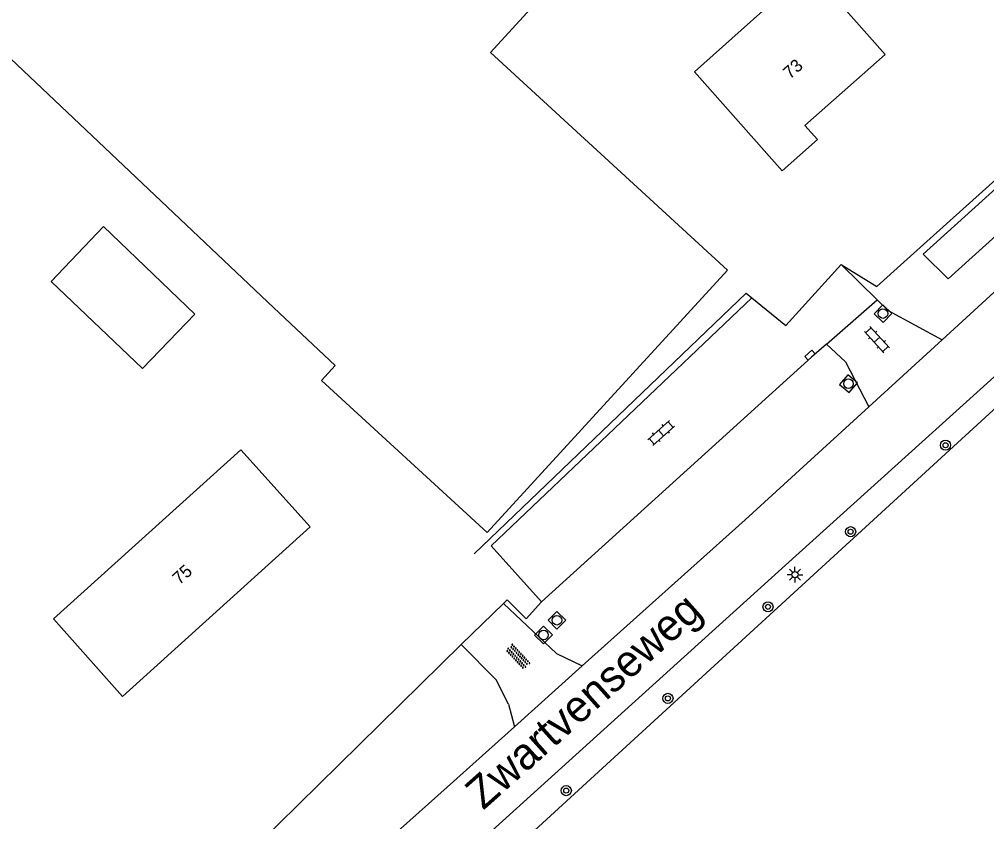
# Model space of a CAD drawing. Extents: x 128999 to 131010, y 395498 to 399007.
# Drawn here: x 129740 to 129816.6, y 397459.3 to 397522.8 of the extents above; entities that cross this region are included whole.
import ezdxf

# ---------------------------------------------------------------- set-up
doc = ezdxf.new("R2010")
doc.units = 0
for name, color, linetype in [('gg-afsc-erfafscheiding', 7, 'Continuous'), ('gg-afsc-hekwerk', 7, 'Continuous'), ('gg-anno-huisnummerreeks BGT', 7, 'Continuous'), ('gg-anno-openbare ruimte label', 7, 'Continuous'), ('gg-bbg-bijgebouw', 7, 'Continuous'), ('gg-bbg-hoofdgebouw', 7, 'Continuous'), ('gg-knt-onverhard', 7, 'Continuous'), ('gg-knt-verharding', 7, 'Continuous'), ('gg-kntw-bovenkant insteek waterloop', 7, 'Continuous'), ('gt-grn-groengrens', 7, 'Continuous'), ('gt-grn-vlakafsluiter', 7, 'Continuous'), ('gt-symb-boom', 7, 'Continuous'), ('gt-symb-klinker verharding', 7, 'Continuous'), ('gt-symb-kolk', 7, 'Continuous'), ('gt-symb-lichtmast', 7, 'Continuous'), ('gt-symb-overige verharding', 7, 'Continuous'), ('gt-symb-rioolschacht', 7, 'Continuous')]:
    doc.layers.add(name, color=color, linetype=linetype)

# ---------------------------------------------------------------- blocks, each defined once
blk = doc.blocks.new('gt0-BOOM')
at = {"layer": 'gt-symb-boom'}
for radius in [0.4, 0.2]:
    blk.add_circle((0, 0), radius, dxfattribs=at)
blk = doc.blocks.new('gt0-RS')
at = {"layer": 'gt-symb-rioolschacht'}
blk.add_lwpolyline([(-0.5, -0.5), (0.5, -0.5), (0.5, 0.5), (-0.5, 0.5)], close=True, dxfattribs=at)
blk.add_circle((0, 0), 0.375, dxfattribs=at)
blk = doc.blocks.new('gt0-LMAST')
at = {"layer": 'gt-symb-lichtmast'}
for p, q in [((-0.182, 0.173), (-0.447, 0.438)), ((-0.005, 0.246), (-0.005, 0.621)), ((0.172, 0.173), (0.437, 0.438)), ((-0.255, -0.004), (-0.63, -0.004)), ((-0.182, -0.181), (-0.447, -0.446)), ((-0.005, -0.254), (-0.005, -0.629)), ((0.437, -0.446), (0.172, -0.181)), ((0.245, -0.004), (0.62, -0.004))]:
    blk.add_line(p, q, dxfattribs=at)
blk.add_circle((-0.005, -0.004), 0.25, dxfattribs=at)
blk = doc.blocks.new('gt0-KL1')
at = {"layer": 'gt-symb-klinker verharding'}
for p, q in [((-1.15, 0.3), (1.15, 0.3)), ((-1, -0.3), (-1, 0.3)), ((-0.5, 0.3), (-0.5, 0.45)), ((0, -0.3), (0, 0.3)), ((0.5, 0.3), (0.5, 0.45)), ((1, -0.3), (1, 0.3)), ((-1.15, -0.3), (1.15, -0.3)), ((-0.5, -0.45), (-0.5, -0.3)), ((0.5, -0.45), (0.5, -0.3))]:
    blk.add_line(p, q, dxfattribs=at)
blk = doc.blocks.new('gt0-KOLK')
at = {"layer": 'gt-symb-kolk'}
blk.add_lwpolyline([(0, 0), (0.375, 0), (0.375, 0.4), (-0.375, 0.4), (-0.375, 0), (0, 0)], dxfattribs=at)
blk = doc.blocks.new('gt0-OVH')
at = {"layer": 'gt-symb-overige verharding'}
for points in [[(-0.972, 0.298), (-0.967, 0.308), (-0.965, 0.319), (-0.966, 0.33), (-0.971, 0.34), (-0.978, 0.348), (-0.988, 0.353), (-0.999, 0.355), (-1.01, 0.354), (-1.02, 0.349), (-1.028, 0.342), (-1.033, 0.332), (-1.035, 0.321), (-1.034, 0.31), (-1.029, 0.3), (-1.022, 0.292), (-1.012, 0.287), (-1.001, 0.285), (-0.99, 0.286), (-0.98, 0.291)], [(-0.872, 0.106), (-0.867, 0.116), (-0.865, 0.126), (-0.866, 0.137), (-0.871, 0.147), (-0.878, 0.156), (-0.888, 0.161), (-0.899, 0.163), (-0.91, 0.162), (-0.92, 0.157), (-0.928, 0.15), (-0.933, 0.14), (-0.935, 0.129), (-0.934, 0.118), (-0.929, 0.108), (-0.922, 0.1), (-0.912, 0.095), (-0.901, 0.092), (-0.89, 0.094), (-0.88, 0.098)], [(-0.772, 0.298), (-0.767, 0.308), (-0.765, 0.319), (-0.766, 0.33), (-0.771, 0.34), (-0.778, 0.348), (-0.788, 0.353), (-0.799, 0.355), (-0.81, 0.354), (-0.82, 0.349), (-0.828, 0.342), (-0.833, 0.332), (-0.835, 0.321), (-0.834, 0.31), (-0.829, 0.3), (-0.822, 0.292), (-0.812, 0.287), (-0.801, 0.285), (-0.79, 0.286), (-0.78, 0.291)], [(-0.672, 0.106), (-0.667, 0.116), (-0.665, 0.126), (-0.666, 0.137), (-0.671, 0.147), (-0.678, 0.156), (-0.688, 0.161), (-0.699, 0.163), (-0.71, 0.162), (-0.72, 0.157), (-0.728, 0.15), (-0.733, 0.14), (-0.735, 0.129), (-0.734, 0.118), (-0.729, 0.108), (-0.722, 0.1), (-0.712, 0.095), (-0.701, 0.092), (-0.69, 0.094), (-0.68, 0.098)], [(-0.572, 0.298), (-0.567, 0.308), (-0.565, 0.319), (-0.566, 0.33), (-0.571, 0.34), (-0.578, 0.348), (-0.588, 0.353), (-0.599, 0.355), (-0.61, 0.354), (-0.62, 0.349), (-0.628, 0.342), (-0.633, 0.332), (-0.635, 0.321), (-0.634, 0.31), (-0.629, 0.3), (-0.622, 0.292), (-0.612, 0.287), (-0.601, 0.285), (-0.59, 0.286), (-0.58, 0.291)], [(-0.472, 0.106), (-0.467, 0.116), (-0.465, 0.126), (-0.466, 0.137), (-0.471, 0.147), (-0.478, 0.156), (-0.488, 0.161), (-0.499, 0.163), (-0.51, 0.162), (-0.52, 0.157), (-0.528, 0.15), (-0.533, 0.14), (-0.535, 0.129), (-0.534, 0.118), (-0.529, 0.108), (-0.522, 0.1), (-0.512, 0.095), (-0.501, 0.092), (-0.49, 0.094), (-0.48, 0.098)], [(-0.372, 0.298), (-0.367, 0.308), (-0.365, 0.319), (-0.366, 0.33), (-0.371, 0.34), (-0.378, 0.348), (-0.388, 0.353), (-0.399, 0.355), (-0.41, 0.354), (-0.42, 0.349), (-0.428, 0.342), (-0.433, 0.332), (-0.435, 0.321), (-0.434, 0.31), (-0.429, 0.3), (-0.422, 0.292), (-0.412, 0.287), (-0.401, 0.285), (-0.39, 0.286), (-0.38, 0.291)], [(-0.272, 0.106), (-0.267, 0.116), (-0.265, 0.126), (-0.266, 0.137), (-0.271, 0.147), (-0.278, 0.156), (-0.288, 0.161), (-0.299, 0.163), (-0.31, 0.162), (-0.32, 0.157), (-0.328, 0.15), (-0.333, 0.14), (-0.335, 0.129), (-0.334, 0.118), (-0.329, 0.108), (-0.322, 0.1), (-0.312, 0.095), (-0.301, 0.092), (-0.29, 0.094), (-0.28, 0.098)], [(-0.172, 0.298), (-0.167, 0.308), (-0.165, 0.319), (-0.166, 0.33), (-0.171, 0.34), (-0.178, 0.348), (-0.188, 0.353), (-0.199, 0.355), (-0.21, 0.354), (-0.22, 0.349), (-0.228, 0.342), (-0.233, 0.332), (-0.235, 0.321), (-0.234, 0.31), (-0.229, 0.3), (-0.222, 0.292), (-0.212, 0.287), (-0.201, 0.285), (-0.19, 0.286), (-0.18, 0.291)], [(-0.072, 0.106), (-0.067, 0.116), (-0.065, 0.126), (-0.066, 0.137), (-0.071, 0.147), (-0.078, 0.156), (-0.088, 0.161), (-0.099, 0.163), (-0.11, 0.162), (-0.12, 0.157), (-0.128, 0.15), (-0.133, 0.14), (-0.135, 0.129), (-0.134, 0.118), (-0.129, 0.108), (-0.122, 0.1), (-0.112, 0.095), (-0.101, 0.092), (-0.09, 0.094), (-0.08, 0.098)], [(0.028, 0.298), (0.033, 0.308), (0.035, 0.319), (0.034, 0.33), (0.029, 0.34), (0.022, 0.348), (0.012, 0.353), (0.001, 0.355), (-0.01, 0.354), (-0.02, 0.349), (-0.028, 0.342), (-0.033, 0.332), (-0.035, 0.321), (-0.034, 0.31), (-0.029, 0.3), (-0.022, 0.292), (-0.012, 0.287), (-0.001, 0.285), (0.01, 0.286), (0.02, 0.291)], [(0.128, 0.106), (0.133, 0.116), (0.135, 0.126), (0.134, 0.137), (0.129, 0.147), (0.122, 0.156), (0.112, 0.161), (0.101, 0.163), (0.09, 0.162), (0.08, 0.157), (0.072, 0.15), (0.067, 0.14), (0.065, 0.129), (0.066, 0.118), (0.071, 0.108), (0.078, 0.1), (0.088, 0.095), (0.099, 0.092), (0.11, 0.094), (0.12, 0.098)], [(0.228, 0.298), (0.233, 0.308), (0.235, 0.319), (0.234, 0.33), (0.229, 0.34), (0.222, 0.348), (0.212, 0.353), (0.201, 0.355), (0.19, 0.354), (0.18, 0.349), (0.172, 0.342), (0.167, 0.332), (0.165, 0.321), (0.166, 0.31), (0.171, 0.3), (0.178, 0.292), (0.188, 0.287), (0.199, 0.285), (0.21, 0.286), (0.22, 0.291)], [(0.328, 0.106), (0.333, 0.116), (0.335, 0.126), (0.334, 0.137), (0.329, 0.147), (0.322, 0.156), (0.312, 0.161), (0.301, 0.163), (0.29, 0.162), (0.28, 0.157), (0.272, 0.15), (0.267, 0.14), (0.265, 0.129), (0.266, 0.118), (0.271, 0.108), (0.278, 0.1), (0.288, 0.095), (0.299, 0.092), (0.31, 0.094), (0.32, 0.098)], [(0.428, 0.298), (0.433, 0.308), (0.435, 0.319), (0.434, 0.33), (0.429, 0.34), (0.422, 0.348), (0.412, 0.353), (0.401, 0.355), (0.39, 0.354), (0.38, 0.349), (0.372, 0.342), (0.367, 0.332), (0.365, 0.321), (0.366, 0.31), (0.371, 0.3), (0.378, 0.292), (0.388, 0.287), (0.399, 0.285), (0.41, 0.286), (0.42, 0.291)], [(0.528, 0.106), (0.533, 0.116), (0.535, 0.126), (0.534, 0.137), (0.529, 0.147), (0.522, 0.156), (0.512, 0.161), (0.501, 0.163), (0.49, 0.162), (0.48, 0.157), (0.472, 0.15), (0.467, 0.14), (0.465, 0.129), (0.466, 0.118), (0.471, 0.108), (0.478, 0.1), (0.488, 0.095), (0.499, 0.092), (0.51, 0.094), (0.52, 0.098)], [(0.628, 0.298), (0.633, 0.308), (0.635, 0.319), (0.634, 0.33), (0.629, 0.34), (0.622, 0.348), (0.612, 0.353), (0.601, 0.355), (0.59, 0.354), (0.58, 0.349), (0.572, 0.342), (0.567, 0.332), (0.565, 0.321), (0.566, 0.31), (0.571, 0.3), (0.578, 0.292), (0.588, 0.287), (0.599, 0.285), (0.61, 0.286), (0.62, 0.291)], [(0.728, 0.106), (0.733, 0.116), (0.735, 0.126), (0.734, 0.137), (0.729, 0.147), (0.722, 0.156), (0.712, 0.161), (0.701, 0.163), (0.69, 0.162), (0.68, 0.157), (0.672, 0.15), (0.667, 0.14), (0.665, 0.129), (0.666, 0.118), (0.671, 0.108), (0.678, 0.1), (0.688, 0.095), (0.699, 0.092), (0.71, 0.094), (0.72, 0.098)], [(0.828, 0.298), (0.833, 0.308), (0.835, 0.319), (0.834, 0.33), (0.829, 0.34), (0.822, 0.348), (0.812, 0.353), (0.801, 0.355), (0.79, 0.354), (0.78, 0.349), (0.772, 0.342), (0.767, 0.332), (0.765, 0.321), (0.766, 0.31), (0.771, 0.3), (0.778, 0.292), (0.788, 0.287), (0.799, 0.285), (0.81, 0.286), (0.82, 0.291)], [(0.928, 0.106), (0.933, 0.116), (0.935, 0.126), (0.934, 0.137), (0.929, 0.147), (0.922, 0.156), (0.912, 0.161), (0.901, 0.163), (0.89, 0.162), (0.88, 0.157), (0.872, 0.15), (0.867, 0.14), (0.865, 0.129), (0.866, 0.118), (0.871, 0.108), (0.878, 0.1), (0.888, 0.095), (0.899, 0.092), (0.91, 0.094), (0.92, 0.098)], [(1.028, 0.298), (1.033, 0.308), (1.035, 0.319), (1.034, 0.33), (1.029, 0.34), (1.022, 0.348), (1.012, 0.353), (1.001, 0.355), (0.99, 0.354), (0.98, 0.349), (0.972, 0.342), (0.967, 0.332), (0.965, 0.321), (0.966, 0.31), (0.971, 0.3), (0.978, 0.292), (0.988, 0.287), (0.999, 0.285), (1.01, 0.286), (1.02, 0.291)], [(-0.972, -0.142), (-0.967, -0.132), (-0.965, -0.121), (-0.966, -0.11), (-0.971, -0.1), (-0.978, -0.092), (-0.988, -0.087), (-0.999, -0.085), (-1.01, -0.086), (-1.02, -0.091), (-1.028, -0.098), (-1.033, -0.108), (-1.035, -0.119), (-1.034, -0.13), (-1.029, -0.14), (-1.022, -0.148), (-1.012, -0.153), (-1.001, -0.155), (-0.99, -0.154), (-0.98, -0.149)], [(-0.872, -0.334), (-0.867, -0.324), (-0.865, -0.314), (-0.866, -0.303), (-0.871, -0.293), (-0.878, -0.284), (-0.888, -0.279), (-0.899, -0.277), (-0.91, -0.278), (-0.92, -0.283), (-0.928, -0.29), (-0.933, -0.3), (-0.935, -0.311), (-0.934, -0.322), (-0.929, -0.332), (-0.922, -0.34), (-0.912, -0.345), (-0.901, -0.348), (-0.89, -0.346), (-0.88, -0.342)], [(-0.772, -0.142), (-0.767, -0.132), (-0.765, -0.121), (-0.766, -0.11), (-0.771, -0.1), (-0.778, -0.092), (-0.788, -0.087), (-0.799, -0.085), (-0.81, -0.086), (-0.82, -0.091), (-0.828, -0.098), (-0.833, -0.108), (-0.835, -0.119), (-0.834, -0.13), (-0.829, -0.14), (-0.822, -0.148), (-0.812, -0.153), (-0.801, -0.155), (-0.79, -0.154), (-0.78, -0.149)], [(-0.672, -0.334), (-0.667, -0.324), (-0.665, -0.314), (-0.666, -0.303), (-0.671, -0.293), (-0.678, -0.284), (-0.688, -0.279), (-0.699, -0.277), (-0.71, -0.278), (-0.72, -0.283), (-0.728, -0.29), (-0.733, -0.3), (-0.735, -0.311), (-0.734, -0.322), (-0.729, -0.332), (-0.722, -0.34), (-0.712, -0.345), (-0.701, -0.348), (-0.69, -0.346), (-0.68, -0.342)], [(-0.572, -0.142), (-0.567, -0.132), (-0.565, -0.121), (-0.566, -0.11), (-0.571, -0.1), (-0.578, -0.092), (-0.588, -0.087), (-0.599, -0.085), (-0.61, -0.086), (-0.62, -0.091), (-0.628, -0.098), (-0.633, -0.108), (-0.635, -0.119), (-0.634, -0.13), (-0.629, -0.14), (-0.622, -0.148), (-0.612, -0.153), (-0.601, -0.155), (-0.59, -0.154), (-0.58, -0.149)], [(-0.472, -0.334), (-0.467, -0.324), (-0.465, -0.314), (-0.466, -0.303), (-0.471, -0.293), (-0.478, -0.284), (-0.488, -0.279), (-0.499, -0.277), (-0.51, -0.278), (-0.52, -0.283), (-0.528, -0.29), (-0.533, -0.3), (-0.535, -0.311), (-0.534, -0.322), (-0.529, -0.332), (-0.522, -0.34), (-0.512, -0.345), (-0.501, -0.348), (-0.49, -0.346), (-0.48, -0.342)], [(-0.372, -0.142), (-0.367, -0.132), (-0.365, -0.121), (-0.366, -0.11), (-0.371, -0.1), (-0.378, -0.092), (-0.388, -0.087), (-0.399, -0.085), (-0.41, -0.086), (-0.42, -0.091), (-0.428, -0.098), (-0.433, -0.108), (-0.435, -0.119), (-0.434, -0.13), (-0.429, -0.14), (-0.422, -0.148), (-0.412, -0.153), (-0.401, -0.155), (-0.39, -0.154), (-0.38, -0.149)], [(-0.272, -0.334), (-0.267, -0.324), (-0.265, -0.314), (-0.266, -0.303), (-0.271, -0.293), (-0.278, -0.284), (-0.288, -0.279), (-0.299, -0.277), (-0.31, -0.278), (-0.32, -0.283), (-0.328, -0.29), (-0.333, -0.3), (-0.335, -0.311), (-0.334, -0.322), (-0.329, -0.332), (-0.322, -0.34), (-0.312, -0.345), (-0.301, -0.348), (-0.29, -0.346), (-0.28, -0.342)], [(-0.172, -0.142), (-0.167, -0.132), (-0.165, -0.121), (-0.166, -0.11), (-0.171, -0.1), (-0.178, -0.092), (-0.188, -0.087), (-0.199, -0.085), (-0.21, -0.086), (-0.22, -0.091), (-0.228, -0.098), (-0.233, -0.108), (-0.235, -0.119), (-0.234, -0.13), (-0.229, -0.14), (-0.222, -0.148), (-0.212, -0.153), (-0.201, -0.155), (-0.19, -0.154), (-0.18, -0.149)], [(-0.072, -0.334), (-0.067, -0.324), (-0.065, -0.314), (-0.066, -0.303), (-0.071, -0.293), (-0.078, -0.284), (-0.088, -0.279), (-0.099, -0.277), (-0.11, -0.278), (-0.12, -0.283), (-0.128, -0.29), (-0.133, -0.3), (-0.135, -0.311), (-0.134, -0.322), (-0.129, -0.332), (-0.122, -0.34), (-0.112, -0.345), (-0.101, -0.348), (-0.09, -0.346), (-0.08, -0.342)], [(0.028, -0.142), (0.033, -0.132), (0.035, -0.121), (0.034, -0.11), (0.029, -0.1), (0.022, -0.092), (0.012, -0.087), (0.001, -0.085), (-0.01, -0.086), (-0.02, -0.091), (-0.028, -0.098), (-0.033, -0.108), (-0.035, -0.119), (-0.034, -0.13), (-0.029, -0.14), (-0.022, -0.148), (-0.012, -0.153), (-0.001, -0.155), (0.01, -0.154), (0.02, -0.149)], [(0.128, -0.334), (0.133, -0.324), (0.135, -0.314), (0.134, -0.303), (0.129, -0.293), (0.122, -0.284), (0.112, -0.279), (0.101, -0.277), (0.09, -0.278), (0.08, -0.283), (0.072, -0.29), (0.067, -0.3), (0.065, -0.311), (0.066, -0.322), (0.071, -0.332), (0.078, -0.34), (0.088, -0.345), (0.099, -0.348), (0.11, -0.346), (0.12, -0.342)], [(0.228, -0.142), (0.233, -0.132), (0.235, -0.121), (0.234, -0.11), (0.229, -0.1), (0.222, -0.092), (0.212, -0.087), (0.201, -0.085), (0.19, -0.086), (0.18, -0.091), (0.172, -0.098), (0.167, -0.108), (0.165, -0.119), (0.166, -0.13), (0.171, -0.14), (0.178, -0.148), (0.188, -0.153), (0.199, -0.155), (0.21, -0.154), (0.22, -0.149)], [(0.328, -0.334), (0.333, -0.324), (0.335, -0.314), (0.334, -0.303), (0.329, -0.293), (0.322, -0.284), (0.312, -0.279), (0.301, -0.277), (0.29, -0.278), (0.28, -0.283), (0.272, -0.29), (0.267, -0.3), (0.265, -0.311), (0.266, -0.322), (0.271, -0.332), (0.278, -0.34), (0.288, -0.345), (0.299, -0.348), (0.31, -0.346), (0.32, -0.342)], [(0.428, -0.142), (0.433, -0.132), (0.435, -0.121), (0.434, -0.11), (0.429, -0.1), (0.422, -0.092), (0.412, -0.087), (0.401, -0.085), (0.39, -0.086), (0.38, -0.091), (0.372, -0.098), (0.367, -0.108), (0.365, -0.119), (0.366, -0.13), (0.371, -0.14), (0.378, -0.148), (0.388, -0.153), (0.399, -0.155), (0.41, -0.154), (0.42, -0.149)], [(0.528, -0.334), (0.533, -0.324), (0.535, -0.314), (0.534, -0.303), (0.529, -0.293), (0.522, -0.284), (0.512, -0.279), (0.501, -0.277), (0.49, -0.278), (0.48, -0.283), (0.472, -0.29), (0.467, -0.3), (0.465, -0.311), (0.466, -0.322), (0.471, -0.332), (0.478, -0.34), (0.488, -0.345), (0.499, -0.348), (0.51, -0.346), (0.52, -0.342)], [(0.628, -0.142), (0.633, -0.132), (0.635, -0.121), (0.634, -0.11), (0.629, -0.1), (0.622, -0.092), (0.612, -0.087), (0.601, -0.085), (0.59, -0.086), (0.58, -0.091), (0.572, -0.098), (0.567, -0.108), (0.565, -0.119), (0.566, -0.13), (0.571, -0.14), (0.578, -0.148), (0.588, -0.153), (0.599, -0.155), (0.61, -0.154), (0.62, -0.149)], [(0.728, -0.334), (0.733, -0.324), (0.735, -0.314), (0.734, -0.303), (0.729, -0.293), (0.722, -0.284), (0.712, -0.279), (0.701, -0.277), (0.69, -0.278), (0.68, -0.283), (0.672, -0.29), (0.667, -0.3), (0.665, -0.311), (0.666, -0.322), (0.671, -0.332), (0.678, -0.34), (0.688, -0.345), (0.699, -0.348), (0.71, -0.346), (0.72, -0.342)], [(0.828, -0.142), (0.833, -0.132), (0.835, -0.121), (0.834, -0.11), (0.829, -0.1), (0.822, -0.092), (0.812, -0.087), (0.801, -0.085), (0.79, -0.086), (0.78, -0.091), (0.772, -0.098), (0.767, -0.108), (0.765, -0.119), (0.766, -0.13), (0.771, -0.14), (0.778, -0.148), (0.788, -0.153), (0.799, -0.155), (0.81, -0.154), (0.82, -0.149)], [(0.928, -0.334), (0.933, -0.324), (0.935, -0.314), (0.934, -0.303), (0.929, -0.293), (0.922, -0.284), (0.912, -0.279), (0.901, -0.277), (0.89, -0.278), (0.88, -0.283), (0.872, -0.29), (0.867, -0.3), (0.865, -0.311), (0.866, -0.322), (0.871, -0.332), (0.878, -0.34), (0.888, -0.345), (0.899, -0.348), (0.91, -0.346), (0.92, -0.342)], [(1.028, -0.142), (1.033, -0.132), (1.035, -0.121), (1.034, -0.11), (1.029, -0.1), (1.022, -0.092), (1.012, -0.087), (1.001, -0.085), (0.99, -0.086), (0.98, -0.091), (0.972, -0.098), (0.967, -0.108), (0.965, -0.119), (0.966, -0.13), (0.971, -0.14), (0.978, -0.148), (0.988, -0.153), (0.999, -0.155), (1.01, -0.154), (1.02, -0.149)]]:
    blk.add_lwpolyline(points, close=True, dxfattribs=at)

msp = doc.modelspace()

# ---------------------------------------------------------------- linework, layer by layer
at = {"layer": 'gg-afsc-erfafscheiding'}
msp.add_line((129778.284, 397476.595), (129774.952, 397473.324), dxfattribs=at)
for points in [[(129780.084, 397475.379), (129778.572, 397476.878), (129778.284, 397476.595)], [(129774.952, 397473.324), (129758.832, 397457.5), (129739.921, 397439.14)]]:
    msp.add_lwpolyline(points, dxfattribs=at)
at = {"layer": 'gg-afsc-hekwerk'}
msp.add_line((129809.996, 397503.61), (129828.73, 397520.433), dxfattribs=at)
for points in [[(129797.963, 397500.771), (129800.656, 397498.579), (129805.024, 397503.422)], [(129805.024, 397503.422), (129807.858, 397501.69), (129809.996, 397503.61)], [(129775.981, 397480.514), (129797.502, 397501.146), (129797.963, 397500.771)]]:
    msp.add_lwpolyline(points, dxfattribs=at)
at = {"layer": 'gg-bbg-bijgebouw'}
for points in [[(129760.109, 397500), (129705.52, 397551.668), (129742.182, 397591.587), (129743.618, 397590.268)], [(129760.109, 397500), (129764.955, 397495.413), (129763.874, 397494.233), (129777, 397482.21), (129796.04, 397502.97), (129777.26, 397520.21), (129809.908, 397555.862)], [(129753.851, 397499.496), (129749.72, 397495.189), (129742.482, 397502.087), (129746.621, 397506.43), (129753.851, 397499.496)]]:
    msp.add_lwpolyline(points, dxfattribs=at)
at = {"layer": 'gg-bbg-hoofdgebouw'}
for points in [[(129802.53, 397526.831), (129793.42, 397518.67), (129800.35, 397510.83), (129803.16, 397513.31), (129802.17, 397514.43)], [(129802.53, 397526.831), (129808.52, 397520.046), (129802.17, 397514.43)], [(129762.99, 397482.65), (129757.49, 397488.74), (129742.67, 397475.38), (129748.12, 397469.23), (129762.99, 397482.65)]]:
    msp.add_lwpolyline(points, dxfattribs=at)
at = {"layer": 'gg-knt-onverhard'}
for p, q in [((129782.487, 397472.635), (129778.284, 397476.595)), ((129782.487, 397472.635), (129784.53, 397471.634)), ((129778.691, 397468.623), (129779.171, 397466.826))]:
    msp.add_line(p, q, dxfattribs=at)
msp.add_lwpolyline([(129778.691, 397468.623), (129777.702, 397470.527), (129774.952, 397473.324)], dxfattribs=at)
at = {"layer": 'gg-knt-verharding'}
for p, q in [((129807.894, 397500.617), (129805.024, 397503.422)), ((129808.745, 397499.786), (129807.894, 397500.617)), ((129808.745, 397499.786), (129813.027, 397497.457)), ((129805.389, 397495.716), (129803.87, 397497.126)), ((129807.227, 397492.157), (129813.027, 397497.457)), ((129805.389, 397495.716), (129807.227, 397492.157)), ((129779.171, 397466.826), (129784.53, 397471.634))]:
    msp.add_line(p, q, dxfattribs=at)
for points in [[(129813.027, 397497.457), (129820.327, 397504.126), (129862.758, 397542.634)], [(129755.566, 397438.488), (129777.094, 397458.341), (129800.626, 397479.621), (129823.614, 397500.365), (129846.09, 397520.844), (129866.108, 397538.931)], [(129781.292, 397476.703), (129777.331, 397481.139), (129797.963, 397500.771)], [(129803.87, 397497.126), (129802.698, 397496.096), (129781.292, 397476.703)], [(129784.53, 397471.634), (129797.421, 397483.198), (129807.227, 397492.157)], [(129779.171, 397466.826), (129773.84, 397462.044), (129750.687, 397441.389), (129744.406, 397435.659), (129742.646, 397434.005)]]:
    msp.add_lwpolyline(points, dxfattribs=at)
at = {"layer": 'gg-kntw-bovenkant insteek waterloop'}
msp.add_lwpolyline([(129811.521, 397504.246), (129813.517, 397502.275), (129831.959, 397518.929), (129829.963, 397520.9), (129811.521, 397504.246)], dxfattribs=at)
at = {"layer": 'gt-grn-groengrens'}
msp.add_lwpolyline([(129740.7, 397416.557), (129741.631, 397417.918), (129744.413, 397422.824), (129747.649, 397427.449), (129754.211, 397434.308), (129819.597, 397494.201)], dxfattribs=at)
at = {"layer": 'gt-grn-vlakafsluiter'}
for p, q in [((129803.87, 397497.126), (129807.894, 397500.617)), ((129781.292, 397476.703), (129780.084, 397475.379))]:
    msp.add_line(p, q, dxfattribs=at)

# ---------------------------------------------------------------- block references
at = {"layer": 'gt-symb-boom'}
for p in [(129813.301, 397489.113), (129805.786, 397482.268), (129799.241, 397476.318), (129791.318, 397469.073), (129783.267, 397461.766)]:
    msp.add_blockref('gt0-BOOM', p, dxfattribs=at)
at = {"layer": 'gt-symb-klinker verharding'}
for p, rotation in [((129807.87, 397497.472), -47.59519959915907), ((129790.778, 397490.081), 41.919064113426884)]:
    msp.add_blockref('gt0-KL1', p, dxfattribs=dict(at, rotation=rotation))
at = {"layer": 'gt-symb-kolk', "rotation": 42.16188122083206}
msp.add_blockref('gt0-KOLK', (129802.698, 397496.096), dxfattribs=at)
at = {"layer": 'gt-symb-lichtmast'}
msp.add_blockref('gt0-LMAST', (129801.382, 397478.867), dxfattribs=at)
at = {"layer": 'gt-symb-overige verharding', "rotation": -46.90510202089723}
msp.add_blockref('gt0-OVH', (129779.439, 397472.373), dxfattribs=at)
at = {"layer": 'gt-symb-rioolschacht'}
for p, rotation in [((129808.346, 397499.534), -44.029945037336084), ((129805.612, 397493.986), 139.541384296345), ((129782.53, 397475.253), 44.91895934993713), ((129781.465, 397474.09), 45.243120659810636)]:
    msp.add_blockref('gt0-RS', p, dxfattribs=dict(at, rotation=rotation))

# ---------------------------------------------------------------- texts
at = {"layer": 'gg-anno-huisnummerreeks BGT'}
for s, rotation, p in [('73', 41.5, (129800.981, 397518.05)), ('75', 42.1, (129752.634, 397478.018))]:
    msp.add_text(s, height=1, rotation=rotation, dxfattribs=at).set_placement(p)
at = {"layer": 'gg-anno-openbare ruimte label'}
msp.add_text('Zwartvenseweg', height=2.5, rotation=41.7, dxfattribs=at).set_placement((129776.693, 397460.179))

doc.saveas('drawing.dxf')
